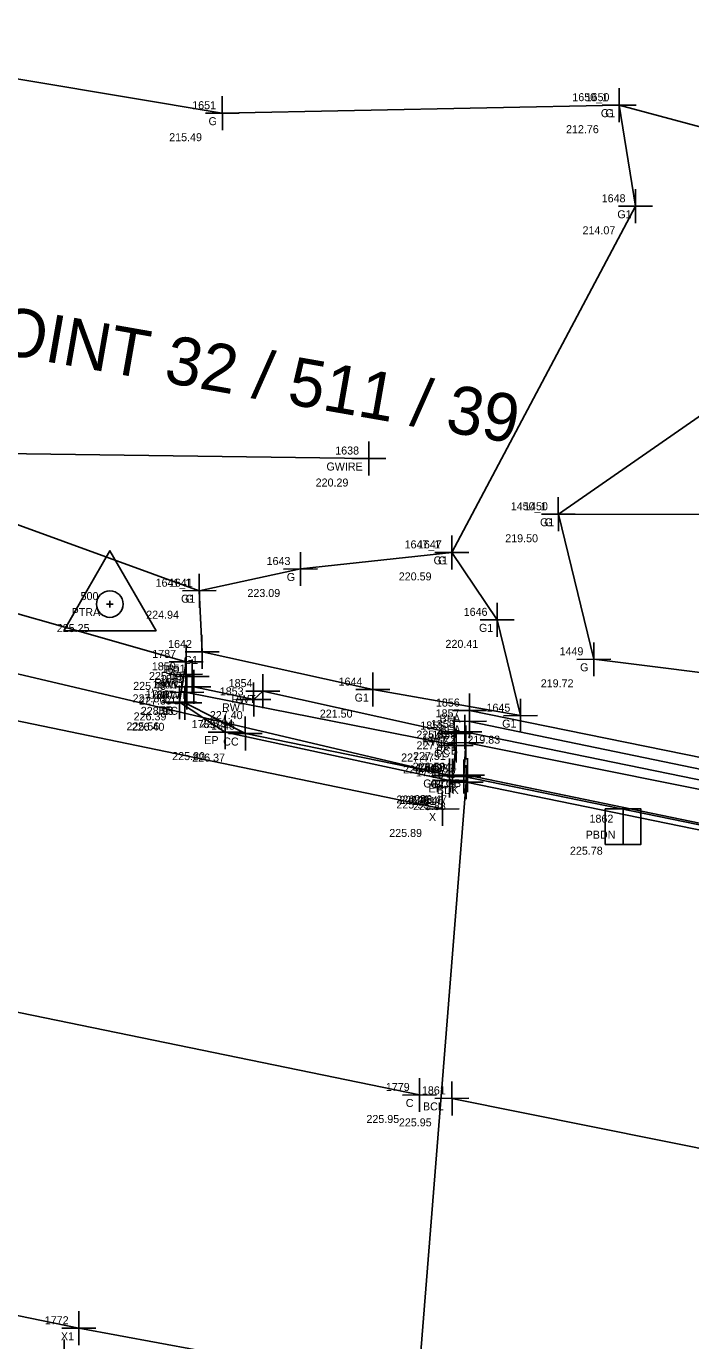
# Model space of a CAD drawing. Extents: x 1158983 to 1160032, y 610902 to 611573.
# Drawn here: x 1159317.32 to 1159342.21, y 611268.4 to 611317.69 of the extents above; entities that cross this region are included whole.
import ezdxf

# ---------------------------------------------------------------- set-up
doc = ezdxf.new("R2010")
doc.units = 0
for name, color, linetype in [('Default', 7, 'Continuous'), ('S_Bridge_Centerline', 7, 'Continuous'), ('S_Bridge_Curb', 7, 'Continuous'), ('S_Bridge_Deck', 7, 'Continuous'), ('S_Bridge_Downspout', 7, 'Continuous'), ('S_Bridge_Fascia', 7, 'Continuous'), ('S_Control_Traverse_Point', 7, 'Continuous'), ('S_Curb_Type_2', 7, 'Continuous'), ('S_Field_Code', 7, 'Continuous'), ('S_Ground_Elevation', 7, 'Continuous'), ('S_Guardrail_Beam', 7, 'Continuous'), ('S_Misc_MiscFeature', 7, 'Continuous'), ('S_Point_Elevation', 7, 'Continuous'), ('S_Point_Name', 7, 'Continuous'), ('S_RetWall_Top', 7, 'Continuous'), ('S_Roadway_Centerline', 7, 'Continuous'), ('S_Roadway_Edge_Pavement', 7, 'Continuous'), ('S_Roadway_Edge_TW', 7, 'Continuous'), ('S_Survey_Shot', 7, 'Continuous'), ('S_Text', 7, 'Continuous'), ('S_Utilities_GuyWire3', 7, 'Continuous')]:
    doc.layers.add(name, color=color, linetype=linetype)

msp = doc.modelspace()

# ---------------------------------------------------------------- linework, layer by layer
at = {"layer": 'Default'}
msp.add_line((1159339.678, 611287.676), (1159339.678, 611287.676), dxfattribs=at)
at = {"layer": 'S_Bridge_Centerline'}
msp.add_lwpolyline([(1159333.269, 611277.49), (1159375.085, 611269.079), (1159432.648, 611257.515), (1159502.769, 611243.159), (1159572.889, 611228.86), (1159630.259, 611216.999), (1159672.294, 611208.379)], dxfattribs=at)
at = {"layer": 'S_Bridge_Curb'}
msp.add_lwpolyline([(1159333.785, 611290.827), (1159333.713, 611289.561), (1159375.839, 611280.908), (1159376.49, 611282.265)], close=True, dxfattribs=at)
at = {"layer": 'S_Bridge_Deck'}
msp.add_lwpolyline([(1159333.801, 611289.348), (1159375.965, 611280.699), (1159433.546, 611269.247), (1159503.551, 611254.972), (1159573.652, 611240.691), (1159630.945, 611229.008), (1159674.004, 611220.503), (1159672.341, 611196.28), (1159630.068, 611204.797), (1159572.75, 611216.514), (1159502.493, 611230.859), (1159432.439, 611245.062), (1159375.072, 611256.503), (1159331.888, 611265.329)], close=True, dxfattribs=at)
at = {"layer": 'S_Bridge_Downspout'}
msp.add_line((1159339.678, 611288.343), (1159339.678, 611287.01), dxfattribs=at)
msp.add_lwpolyline([(1159339.012, 611288.343), (1159340.345, 611288.343), (1159340.345, 611287.01), (1159339.012, 611287.01)], close=True, dxfattribs=at)
at = {"layer": 'S_Bridge_Fascia'}
msp.add_lwpolyline([(1159333.923, 611292.031), (1159333.93, 611291.626), (1159376.546, 611282.801), (1159376.534, 611283.357)], close=True, dxfattribs=at)
at = {"layer": 'S_Control_Traverse_Point'}
for p, q in [((1159320.452, 611296.148), (1159320.452, 611295.898)), ((1159320.327, 611296.023), (1159320.577, 611296.023))]:
    msp.add_line(p, q, dxfattribs=at)
msp.add_lwpolyline([(1159318.723, 611295.025), (1159322.181, 611295.025), (1159320.452, 611298.019)], close=True, dxfattribs=at)
msp.add_circle((1159320.452, 611296.023), 0.499, dxfattribs=at)
at = {"layer": 'S_Curb_Type_2'}
msp.add_lwpolyline([(1159333.427, 611290.724), (1159323.332, 611292.712), (1159323.257, 611292.321), (1159325.528, 611291.168), (1159333.291, 611289.582)], close=True, dxfattribs=at)
at = {"layer": 'S_Ground_Elevation'}
for points in [[(1159366.84, 611572.506), (1159350.471, 611523.657), (1159338.484, 611491.874), (1159327.308, 611461.853), (1159319.303, 611430.663), (1159324.274, 611410.669), (1159335.989, 611392.955), (1159341.308, 611378.939), (1159344.811, 611357.612), (1159350.212, 611325.577), (1159356.223, 611311.934), (1159358.143, 611294.408), (1159357.674, 611289.159), (1159344.861, 611293.167), (1159338.584, 611293.952), (1159337.254, 611299.39), (1159348.329, 611299.371), (1159356.747, 611302.3)], [(1159352.149, 611311.344), (1159339.531, 611314.728), (1159324.665, 611314.427), (1159313.821, 611316.237), (1159300.045, 611315.663), (1159295.131, 611328.971), (1159291.342, 611351.557), (1159307.492, 611346.1), (1159310.1, 611324.165)], [(1159281.814, 611347.99), (1159279.491, 611333.481), (1159281.536, 611323.046), (1159282.88, 611313.648), (1159290.494, 611310.007), (1159297.852, 611307.481), (1159311.956, 611300.827), (1159323.804, 611296.524), (1159327.594, 611297.338), (1159333.265, 611297.96)], [(1159323.804, 611296.524), (1159323.906, 611294.227), (1159330.307, 611292.816), (1159335.834, 611291.839), (1159334.965, 611295.431), (1159333.265, 611297.96), (1159340.149, 611310.937), (1159339.531, 611314.728)], [(1159337.254, 611299.39), (1159344.449, 611304.392), (1159354.862, 611309.362)]]:
    msp.add_lwpolyline(points, dxfattribs=at)
at = {"layer": 'S_Guardrail_Beam'}
msp.add_line((1159333.846, 611289.608), (1159375.839, 611280.908), dxfattribs=at)
msp.add_lwpolyline([(1159275.939, 611307.136), (1159288.272, 611302.132), (1159301.161, 611297.793), (1159312.728, 611294.402), (1159333.178, 611289.596)], dxfattribs=at)
at = {"layer": 'S_Misc_MiscFeature'}
msp.add_lwpolyline([(1159333.75, 611291.228), (1159376.477, 611282.47)], dxfattribs=at)
at = {"layer": 'S_RetWall_Top'}
msp.add_lwpolyline([(1159323.292, 611293.389), (1159323.536, 611293.307), (1159323.6, 611292.918), (1159325.841, 611292.45), (1159326.188, 611292.76), (1159333.354, 611291.17)], dxfattribs=at)
at = {"layer": 'S_Roadway_Centerline'}
msp.add_lwpolyline([(1159006.602, 611348.691), (1159057.735, 611336.354), (1159096.909, 611327.465), (1159130.176, 611319.741), (1159165.906, 611311.781), (1159220.187, 611300.272), (1159273.601, 611289.244), (1159316.176, 611280.885), (1159332.053, 611277.617)], dxfattribs=at)
at = {"layer": 'S_Roadway_Edge_Pavement'}
msp.add_lwpolyline([(1159010.626, 611363.406), (1159061.319, 611351.387), (1159100.337, 611342.028), (1159133.857, 611334.48), (1159169.141, 611326.651), (1159225.717, 611315.753), (1159228.967, 611317.398), (1159231.047, 611319.517), (1159252.68, 611317.317), (1159261.737, 611314.051), (1159263.333, 611313.256), (1159275.665, 611310.381), (1159289.771, 611305.203), (1159302.246, 611300.284), (1159312.093, 611297.059), (1159323.315, 611293.855), (1159323.064, 611292.34), (1159324.775, 611291.223), (1159333.176, 611289.409)], dxfattribs=at)
at = {"layer": 'S_Roadway_Edge_TW'}
for points in [[(1159009.832, 611359.245), (1159060.49, 611346.863), (1159099.079, 611338.191), (1159133.188, 611330.52), (1159167.952, 611322.679), (1159223.507, 611310.762), (1159275.252, 611300.093), (1159314.324, 611292.191), (1159332.908, 611288.341)], [(1159003.943, 611338.028), (1159051.315, 611326.497), (1159095.593, 611316.459), (1159127.862, 611309.062), (1159159.052, 611302.124), (1159217.512, 611289.831), (1159271.817, 611278.631), (1159319.29, 611268.871), (1159331.181, 611266.673)]]:
    msp.add_lwpolyline(points, dxfattribs=at)
at = {"layer": 'S_Survey_Shot'}
for p, q in [((1159339.532, 611314.092), (1159339.529, 611315.365)), ((1159339.532, 611314.092), (1159339.529, 611315.365)), ((1159324.666, 611313.791), (1159324.664, 611315.064)), ((1159324.029, 611314.426), (1159325.301, 611314.429)), ((1159324.665, 611314.427), (1159324.665, 611314.427)), ((1159338.894, 611314.727), (1159340.167, 611314.73)), ((1159338.894, 611314.727), (1159340.167, 611314.73)), ((1159339.531, 611314.728), (1159339.531, 611314.728)), ((1159339.531, 611314.728), (1159339.531, 611314.728)), ((1159340.15, 611310.301), (1159340.148, 611311.574)), ((1159339.513, 611310.936), (1159340.785, 611310.939)), ((1159340.149, 611310.937), (1159340.149, 611310.937)), ((1159330.153, 611300.844), (1159330.15, 611302.116)), ((1159329.515, 611301.478), (1159330.788, 611301.481)), ((1159330.151, 611301.48), (1159330.151, 611301.48)), ((1159337.255, 611298.754), (1159337.253, 611300.026)), ((1159337.255, 611298.754), (1159337.253, 611300.026)), ((1159336.618, 611299.389), (1159337.89, 611299.392)), ((1159336.618, 611299.389), (1159337.89, 611299.392)), ((1159337.254, 611299.39), (1159337.254, 611299.39)), ((1159337.254, 611299.39), (1159337.254, 611299.39)), ((1159333.266, 611297.324), (1159333.263, 611298.597)), ((1159333.266, 611297.324), (1159333.263, 611298.597)), ((1159327.596, 611296.702), (1159327.593, 611297.974)), ((1159332.628, 611297.959), (1159333.901, 611297.962)), ((1159332.628, 611297.959), (1159333.901, 611297.962)), ((1159333.265, 611297.96), (1159333.265, 611297.96)), ((1159333.265, 611297.96), (1159333.265, 611297.96)), ((1159323.805, 611295.888), (1159323.803, 611297.16)), ((1159323.805, 611295.888), (1159323.803, 611297.16)), ((1159326.958, 611297.337), (1159328.231, 611297.339)), ((1159327.594, 611297.338), (1159327.594, 611297.338)), ((1159323.168, 611296.523), (1159324.44, 611296.526)), ((1159323.168, 611296.523), (1159324.44, 611296.526)), ((1159323.804, 611296.524), (1159323.804, 611296.524)), ((1159323.804, 611296.524), (1159323.804, 611296.524)), ((1159334.966, 611294.795), (1159334.964, 611296.067)), ((1159334.329, 611295.43), (1159335.601, 611295.432)), ((1159334.965, 611295.431), (1159334.965, 611295.431)), ((1159323.907, 611293.591), (1159323.904, 611294.864)), ((1159323.269, 611294.226), (1159324.542, 611294.229)), ((1159323.317, 611293.218), (1159323.314, 611294.491)), ((1159323.906, 611294.227), (1159323.906, 611294.227)), ((1159338.586, 611293.315), (1159338.583, 611294.588)), ((1159322.679, 611293.853), (1159323.952, 611293.856)), ((1159323.294, 611292.752), (1159323.291, 611294.025)), ((1159323.315, 611293.855), (1159323.315, 611293.855)), ((1159323.538, 611292.671), (1159323.535, 611293.944)), ((1159337.948, 611293.95), (1159339.221, 611293.953)), ((1159338.584, 611293.952), (1159338.584, 611293.952)), ((1159322.656, 611293.387), (1159323.929, 611293.39)), ((1159322.9, 611293.306), (1159324.173, 611293.309)), ((1159323.292, 611293.389), (1159323.292, 611293.389)), ((1159323.334, 611292.076), (1159323.331, 611293.349)), ((1159323.536, 611293.307), (1159323.536, 611293.307)), ((1159323.601, 611292.281), (1159323.598, 611293.554)), ((1159326.189, 611292.124), (1159326.186, 611293.397)), ((1159330.308, 611292.18), (1159330.305, 611293.453)), ((1159322.696, 611292.711), (1159323.968, 611292.714)), ((1159322.963, 611292.916), (1159324.236, 611292.919)), ((1159323.066, 611291.704), (1159323.063, 611292.976)), ((1159323.258, 611291.685), (1159323.255, 611292.957)), ((1159323.332, 611292.712), (1159323.332, 611292.712)), ((1159323.6, 611292.918), (1159323.6, 611292.918)), ((1159325.551, 611292.759), (1159326.824, 611292.762)), ((1159325.842, 611291.813), (1159325.839, 611293.086)), ((1159326.188, 611292.76), (1159326.188, 611292.76)), ((1159329.67, 611292.815), (1159330.943, 611292.818)), ((1159330.307, 611292.816), (1159330.307, 611292.816)), ((1159322.428, 611292.339), (1159323.701, 611292.342)), ((1159322.62, 611292.32), (1159323.893, 611292.322)), ((1159323.064, 611292.34), (1159323.064, 611292.34)), ((1159323.257, 611292.321), (1159323.257, 611292.321)), ((1159325.205, 611292.448), (1159326.477, 611292.451)), ((1159325.841, 611292.45), (1159325.841, 611292.45)), ((1159333.925, 611291.395), (1159333.922, 611292.667)), ((1159333.931, 611290.989), (1159333.928, 611292.262)), ((1159335.835, 611291.202), (1159335.833, 611292.475)), ((1159324.777, 611290.587), (1159324.774, 611291.86)), ((1159325.529, 611290.532), (1159325.526, 611291.805)), ((1159333.287, 611292.03), (1159334.56, 611292.032)), ((1159333.355, 611290.533), (1159333.352, 611291.806)), ((1159333.751, 611290.592), (1159333.749, 611291.864)), ((1159333.923, 611292.031), (1159333.923, 611292.031)), ((1159335.198, 611291.837), (1159336.47, 611291.84)), ((1159335.834, 611291.839), (1159335.834, 611291.839)), ((1159324.139, 611291.222), (1159325.412, 611291.225)), ((1159324.775, 611291.223), (1159324.775, 611291.223)), ((1159333.114, 611291.227), (1159334.386, 611291.229)), ((1159333.293, 611291.624), (1159334.566, 611291.627)), ((1159333.428, 611290.088), (1159333.425, 611291.361)), ((1159333.75, 611291.228), (1159333.75, 611291.228)), ((1159333.786, 611290.191), (1159333.784, 611291.464)), ((1159333.93, 611291.626), (1159333.93, 611291.626)), ((1159324.891, 611291.167), (1159326.164, 611291.17)), ((1159325.528, 611291.168), (1159325.528, 611291.168)), ((1159332.717, 611291.168), (1159333.99, 611291.171)), ((1159332.79, 611290.723), (1159334.063, 611290.726)), ((1159333.149, 611290.826), (1159334.421, 611290.829)), ((1159333.354, 611291.17), (1159333.354, 611291.17)), ((1159333.427, 611290.724), (1159333.427, 611290.724)), ((1159333.785, 611290.827), (1159333.785, 611290.827)), ((1159333.18, 611288.96), (1159333.177, 611290.232)), ((1159333.293, 611288.945), (1159333.29, 611290.218)), ((1159333.848, 611288.972), (1159333.845, 611290.244)), ((1159333.177, 611288.773), (1159333.175, 611290.046)), ((1159333.714, 611288.925), (1159333.711, 611290.198)), ((1159333.803, 611288.712), (1159333.8, 611289.985)), ((1159332.54, 611289.408), (1159333.812, 611289.411)), ((1159332.542, 611289.595), (1159333.815, 611289.597)), ((1159332.655, 611289.58), (1159333.928, 611289.583)), ((1159333.077, 611289.56), (1159334.349, 611289.563)), ((1159333.165, 611289.347), (1159334.438, 611289.35)), ((1159333.176, 611289.409), (1159333.176, 611289.409)), ((1159333.178, 611289.596), (1159333.178, 611289.596)), ((1159333.21, 611289.607), (1159334.483, 611289.609)), ((1159333.291, 611289.582), (1159333.291, 611289.582)), ((1159333.713, 611289.561), (1159333.713, 611289.561)), ((1159333.801, 611289.348), (1159333.801, 611289.348)), ((1159333.846, 611289.608), (1159333.846, 611289.608)), ((1159332.909, 611287.704), (1159332.906, 611288.977)), ((1159332.271, 611288.339), (1159333.544, 611288.342)), ((1159332.908, 611288.341), (1159332.908, 611288.341)), ((1159332.054, 611276.981), (1159332.052, 611278.253)), ((1159333.271, 611276.854), (1159333.268, 611278.127)), ((1159331.417, 611277.615), (1159332.689, 611277.618)), ((1159332.053, 611277.617), (1159332.053, 611277.617)), ((1159332.633, 611277.489), (1159333.906, 611277.492)), ((1159333.269, 611277.49), (1159333.269, 611277.49)), ((1159319.291, 611268.235), (1159319.289, 611269.507)), ((1159318.654, 611268.87), (1159319.926, 611268.872)), ((1159319.29, 611268.871), (1159319.29, 611268.871)), ((1159318.742, 611267.183), (1159318.739, 611268.455))]:
    msp.add_line(p, q, dxfattribs=at)
at = {"layer": 'S_Utilities_GuyWire3'}
msp.add_line((1159330.151, 611301.48), (1159330.151, 611301.48), dxfattribs=at)
msp.add_lwpolyline([(1159330.151, 611301.48), (1159314.567, 611301.697)], dxfattribs=at)

# ---------------------------------------------------------------- texts
at = {"layer": 'S_Field_Code'}
for s, p in [('G1', (1159338.846, 611314.278)), ('G', (1159339.016, 611314.278)), ('G', (1159324.15, 611313.977)), ('G1', (1159339.464, 611310.487)), ('GWIRE', (1159328.567, 611301.03)), ('G1', (1159336.569, 611298.94)), ('G', (1159336.739, 611298.94)), ('G1', (1159332.58, 611297.51)), ('G', (1159332.75, 611297.51)), ('G', (1159327.08, 611296.888)), ('G1', (1159323.119, 611296.074)), ('G', (1159323.289, 611296.074)), ('PTRA', (1159319.02, 611295.573)), ('G1', (1159334.28, 611294.981)), ('EP', (1159322.529, 611293.405)), ('G1', (1159323.221, 611293.777)), ('G', (1159338.069, 611293.502)), ('RWT', (1159322.107, 611292.939)), ('RWT', (1159322.351, 611292.857)), ('RWT', (1159322.414, 611292.468)), ('EP', (1159322.278, 611291.89)), ('CC', (1159322.503, 611292.262)), ('RWT', (1159324.655, 611292)), ('RWT', (1159325.002, 611292.31)), ('G1', (1159329.622, 611292.366)), ('CC', (1159322.427, 611291.871)), ('BFA', (1159332.806, 611291.581)), ('G1', (1159335.149, 611291.389)), ('BFA', (1159332.812, 611291.176)), ('EP', (1159323.989, 611290.773)), ('CC', (1159324.698, 611290.718)), ('RWT', (1159332.168, 611290.72)), ('ZZ', (1159332.949, 611290.778)), ('CC', (1159332.597, 611290.274)), ('BCB', (1159332.67, 611290.377)), ('GB1', (1159332.193, 611289.146)), ('EP', (1159332.389, 611288.959)), ('CC', (1159332.462, 611289.132)), ('BCB', (1159332.598, 611289.111)), ('GB', (1159333.031, 611289.158)), ('BDK', (1159332.701, 611288.898)), ('X', (1159332.407, 611287.891)), ('PBDN', (1159338.278, 611287.226)), ('C', (1159331.538, 611277.167)), ('BCL', (1159332.183, 611277.04)), ('X1', (1159318.619, 611268.421))]:
    msp.add_text(s, height=0.3, dxfattribs=at).set_placement(p)
at = {"layer": 'S_Point_Elevation'}
for s, p in [('212.76', (1159337.542, 611313.678)), ('212.76', (1159337.542, 611313.678)), ('215.49', (1159322.676, 611313.377)), ('214.07', (1159338.16, 611309.887)), ('220.29', (1159328.162, 611300.43)), ('219.50', (1159335.265, 611298.34)), ('219.50', (1159335.265, 611298.34)), ('220.59', (1159331.276, 611296.91)), ('220.59', (1159331.276, 611296.91)), ('223.09', (1159325.606, 611296.288)), ('224.94', (1159321.815, 611295.474)), ('224.94', (1159321.815, 611295.474)), ('225.25', (1159318.463, 611294.973)), ('220.41', (1159333.026, 611294.381)), ('225.00', (1159321.917, 611293.177)), ('219.72', (1159336.595, 611292.902)), ('225.43', (1159321.327, 611292.805)), ('227.38', (1159321.303, 611292.339)), ('227.37', (1159321.547, 611292.257)), ('226.39', (1159321.343, 611291.662)), ('228.93', (1159321.611, 611291.868)), ('228.94', (1159323.852, 611291.4)), ('227.40', (1159324.199, 611291.71)), ('221.50', (1159328.318, 611291.766)), ('225.56', (1159321.075, 611291.29)), ('226.40', (1159321.268, 611291.271)), ('225.02', (1159331.935, 611290.981)), ('227.48', (1159331.941, 611290.576)), ('219.83', (1159333.845, 611290.789)), ('225.80', (1159322.787, 611290.173)), ('226.37', (1159323.539, 611290.118)), ('227.47', (1159331.365, 611290.12)), ('227.51', (1159331.811, 611290.178)), ('226.46', (1159331.438, 611289.674)), ('226.50', (1159331.796, 611289.777)), ('226.46', (1159331.189, 611288.546)), ('226.43', (1159331.302, 611288.532)), ('226.46', (1159331.724, 611288.511)), ('226.47', (1159331.857, 611288.558)), ('225.93', (1159331.187, 611288.359)), ('225.88', (1159331.812, 611288.298)), ('225.89', (1159330.919, 611287.291)), ('225.78', (1159337.689, 611286.626)), ('225.95', (1159330.064, 611276.567)), ('225.95', (1159331.281, 611276.44))]:
    msp.add_text(s, height=0.3, dxfattribs=at).set_placement(p)
at = {"layer": 'S_Point_Name'}
for s, p in [('1651', (1159323.538, 611314.577)), ('1650_1', (1159337.778, 611314.878)), ('1650', (1159338.276, 611314.878)), ('1648', (1159338.878, 611311.087)), ('1638', (1159328.895, 611301.63)), ('1450_1', (1159335.473, 611299.54)), ('1450', (1159335.971, 611299.54)), ('1647_1', (1159331.493, 611298.11)), ('1647', (1159331.992, 611298.11)), ('1643', (1159326.324, 611297.488)), ('1641_1', (1159322.165, 611296.674)), ('1641', (1159322.663, 611296.674)), ('500', (1159319.356, 611296.173)), ('1646', (1159333.708, 611295.581)), ('1642', (1159322.635, 611294.377)), ('1787', (1159322.04, 611294.005)), ('1449', (1159337.299, 611294.102)), ('1850', (1159322.024, 611293.539)), ('1851', (1159322.395, 611293.457)), ('1846', (1159322.061, 611292.862)), ('1852', (1159322.329, 611293.068)), ('1854', (1159324.903, 611292.91)), ('1644', (1159329.022, 611292.966)), ('1788', (1159321.791, 611292.49)), ('1847', (1159321.969, 611292.471)), ('1853', (1159324.57, 611292.6)), ('1856', (1159332.667, 611292.181)), ('1645', (1159334.563, 611291.989)), ('1857', (1159332.656, 611291.776)), ('1789', (1159323.517, 611291.373)), ('1848', (1159324.243, 611291.318)), ('1855', (1159332.083, 611291.32)), ('1858', (1159332.479, 611291.378)), ('1859', (1159332.528, 611290.977)), ('1845', (1159332.142, 611290.874)), ('1786', (1159331.919, 611289.746)), ('1790', (1159331.92, 611289.559)), ('1849', (1159332.021, 611289.732)), ('1860', (1159332.459, 611289.711)), ('1843', (1159332.516, 611289.498)), ('1844', (1159332.547, 611289.758)), ('1781', (1159331.765, 611288.491)), ('1862', (1159338.422, 611287.826)), ('1779', (1159330.792, 611277.767)), ('1861', (1159332.143, 611277.64)), ('1772', (1159318.015, 611269.021))]:
    msp.add_text(s, height=0.3, dxfattribs=at).set_placement(p)
at = {"layer": 'S_Text'}
msp.add_text('JOINT 32 / 511 / 39', height=1.8, rotation=350.044, dxfattribs=at).set_placement((1159314.924, 611305.666))

doc.saveas('drawing.dxf')
